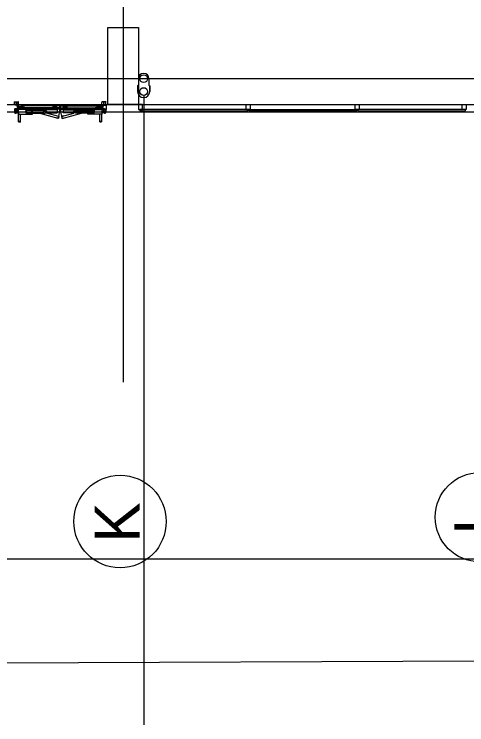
# Model space of a CAD drawing. Extents: x -264031 to -263588, y -1242281 to -1242059.
# Drawn here: x -263850.59 to -263841.78, y -1242253.37 to -1242239.55 of the extents above; entities that cross this region are included whole.
import ezdxf

# ---------------------------------------------------------------- set-up
doc = ezdxf.new("R2010")
doc.units = 0
for name, color, linetype in [('HESCON_OSI_STAVBY_KFA', 7, 'Continuous'), ('KFA_2D_SITUACIA_DSP', 7, 'Continuous'), ('KFA_JESTV_IS_DSP_-_KANAL_SPLASK', 7, 'Continuous')]:
    doc.layers.add(name, color=color, linetype=linetype)

msp = doc.modelspace()

# ---------------------------------------------------------------- linework, layer by layer
at = {"layer": 'HESCON_OSI_STAVBY_KFA'}
for p, q in [((-263848.468, -1242083.237), (-263848.468, -1242246.707)), ((-263792.653, -1242240.807), (-263911.523, -1242240.807))]:
    msp.add_line(p, q, dxfattribs=at)
for centre, radius in [((-263848.528, -1242249.416), 0.899), ((-263841.528, -1242249.331), 0.867)]:
    msp.add_circle(centre, radius, dxfattribs=at)
at = {"layer": 'KFA_2D_SITUACIA_DSP'}
for p, q in [((-263848.768, -1242241.312), (-263848.768, -1242239.812)), ((-263848.768, -1242239.812), (-263848.168, -1242239.812)), ((-263848.168, -1242239.812), (-263848.168, -1242241.312)), ((-263848.171, -1242240.807), (-263848.171, -1242240.932)), ((-263847.965, -1242240.807), (-263847.965, -1242240.932)), ((-263848.171, -1242240.932), (-263848.185, -1242240.946)), ((-263848.185, -1242240.946), (-263848.185, -1242241.057)), ((-263847.965, -1242240.932), (-263847.951, -1242240.946)), ((-263847.951, -1242240.946), (-263847.951, -1242241.057)), ((-263847.951, -1242241.057), (-263847.951, -1242240.946)), ((-263850.587, -1242241.257), (-263850.511, -1242241.257)), ((-263850.581, -1242241.317), (-263850.581, -1242241.257)), ((-263848.798, -1242241.257), (-263848.874, -1242241.257)), ((-263848.804, -1242241.317), (-263848.804, -1242241.257)), ((-263848.068, -1242241.132), (-263848.068, -1242253.366)), ((-263894.581, -1242241.307), (-263809.355, -1242241.307)), ((-263849.693, -1242241.317), (-263850.587, -1242241.317)), ((-263849.693, -1242241.397), (-263850.587, -1242241.397)), ((-263850.582, -1242241.397), (-263850.582, -1242241.407)), ((-263850.582, -1242241.397), (-263850.512, -1242241.397)), ((-263850.571, -1242241.325), (-263850.571, -1242241.317)), ((-263850.55, -1242241.325), (-263850.571, -1242241.325)), ((-263850.55, -1242241.39), (-263850.571, -1242241.39)), ((-263850.571, -1242241.397), (-263850.571, -1242241.39)), ((-263850.554, -1242241.282), (-263850.528, -1242241.282)), ((-263850.541, -1242241.295), (-263850.541, -1242241.269)), ((-263850.512, -1242241.397), (-263850.512, -1242241.407)), ((-263850.507, -1242241.397), (-263850.507, -1242241.317)), ((-263850.507, -1242241.345), (-263850.507, -1242241.37)), ((-263850.507, -1242241.345), (-263850.497, -1242241.345)), ((-263850.507, -1242241.37), (-263850.497, -1242241.37)), ((-263850.462, -1242241.383), (-263850.502, -1242241.383)), ((-263850.502, -1242241.413), (-263850.502, -1242241.383)), ((-263850.501, -1242241.317), (-263850.501, -1242241.267)), ((-263850.501, -1242241.397), (-263850.501, -1242241.317)), ((-263850.501, -1242241.413), (-263850.501, -1242241.397)), ((-263850.497, -1242241.345), (-263850.497, -1242241.37)), ((-263850.497, -1242241.356), (-263850.488, -1242241.349)), ((-263850.497, -1242241.358), (-263850.497, -1242241.356)), ((-263850.488, -1242241.365), (-263850.497, -1242241.358)), ((-263850.494, -1242241.373), (-263850.469, -1242241.373)), ((-263850.494, -1242241.383), (-263850.494, -1242241.373)), ((-263850.494, -1242241.383), (-263850.469, -1242241.383)), ((-263850.49, -1242241.363), (-263850.483, -1242241.373)), ((-263850.483, -1242241.373), (-263850.481, -1242241.373)), ((-263850.481, -1242241.373), (-263850.474, -1242241.363)), ((-263850.478, -1242241.367), (-263850.467, -1242241.362)), ((-263850.476, -1242241.349), (-263850.466, -1242241.356)), ((-263850.466, -1242241.358), (-263850.476, -1242241.365)), ((-263850.467, -1242241.36), (-263850.474, -1242241.351)), ((-263850.47, -1242241.373), (-263850.464, -1242241.349)), ((-263850.461, -1242241.376), (-263850.47, -1242241.373)), ((-263850.469, -1242241.383), (-263850.469, -1242241.373)), ((-263850.467, -1242241.362), (-263850.467, -1242241.36)), ((-263850.456, -1242241.345), (-263850.466, -1242241.345)), ((-263850.466, -1242241.345), (-263850.466, -1242241.37)), ((-263850.466, -1242241.356), (-263850.466, -1242241.358)), ((-263850.456, -1242241.37), (-263850.466, -1242241.37)), ((-263850.454, -1242241.352), (-263850.464, -1242241.349)), ((-263850.452, -1242241.345), (-263850.463, -1242241.383)), ((-263850.41, -1242241.397), (-263850.463, -1242241.383)), ((-263850.462, -1242241.412), (-263850.462, -1242241.383)), ((-263849.698, -1242241.337), (-263850.456, -1242241.337)), ((-263850.456, -1242241.377), (-263850.456, -1242241.337)), ((-263850.456, -1242241.345), (-263850.456, -1242241.37)), ((-263849.698, -1242241.377), (-263850.456, -1242241.377)), ((-263850.255, -1242241.397), (-263850.452, -1242241.345)), ((-263849.755, -1242241.343), (-263849.83, -1242241.343)), ((-263849.83, -1242241.397), (-263849.83, -1242241.343)), ((-263849.83, -1242241.403), (-263849.83, -1242241.397)), ((-263849.819, -1242241.35), (-263849.823, -1242241.357)), ((-263849.823, -1242241.357), (-263849.819, -1242241.364)), ((-263849.812, -1242241.35), (-263849.819, -1242241.35)), ((-263849.819, -1242241.364), (-263849.812, -1242241.364)), ((-263849.808, -1242241.357), (-263849.812, -1242241.35)), ((-263849.812, -1242241.364), (-263849.808, -1242241.357)), ((-263849.774, -1242241.35), (-263849.778, -1242241.357)), ((-263849.778, -1242241.357), (-263849.774, -1242241.364)), ((-263849.767, -1242241.35), (-263849.774, -1242241.35)), ((-263849.774, -1242241.364), (-263849.767, -1242241.364)), ((-263849.763, -1242241.357), (-263849.767, -1242241.35)), ((-263849.767, -1242241.364), (-263849.763, -1242241.357)), ((-263849.755, -1242241.397), (-263849.755, -1242241.343)), ((-263849.755, -1242241.403), (-263849.755, -1242241.397)), ((-263849.7, -1242241.335), (-263849.73, -1242241.335)), ((-263849.73, -1242241.337), (-263849.73, -1242241.335)), ((-263849.73, -1242241.379), (-263849.73, -1242241.377)), ((-263849.7, -1242241.379), (-263849.73, -1242241.379)), ((-263849.715, -1242241.38), (-263849.715, -1242241.377)), ((-263849.7, -1242241.374), (-263849.7, -1242241.383)), ((-263849.698, -1242241.377), (-263849.698, -1242241.337)), ((-263849.696, -1242241.375), (-263849.696, -1242241.339)), ((-263849.693, -1242241.317), (-263848.798, -1242241.317)), ((-263849.693, -1242241.397), (-263848.798, -1242241.397)), ((-263849.69, -1242241.375), (-263849.69, -1242241.339)), ((-263849.688, -1242241.337), (-263848.929, -1242241.337)), ((-263849.688, -1242241.377), (-263849.688, -1242241.337)), ((-263849.688, -1242241.377), (-263848.929, -1242241.377)), ((-263849.686, -1242241.335), (-263849.656, -1242241.335)), ((-263849.686, -1242241.374), (-263849.686, -1242241.383)), ((-263849.686, -1242241.379), (-263849.656, -1242241.379)), ((-263849.671, -1242241.38), (-263849.671, -1242241.377)), ((-263849.656, -1242241.337), (-263849.656, -1242241.335)), ((-263849.656, -1242241.379), (-263849.656, -1242241.377)), ((-263849.63, -1242241.343), (-263849.555, -1242241.343)), ((-263849.63, -1242241.397), (-263849.63, -1242241.343)), ((-263849.63, -1242241.403), (-263849.63, -1242241.397)), ((-263849.623, -1242241.357), (-263849.619, -1242241.35)), ((-263849.619, -1242241.364), (-263849.623, -1242241.357)), ((-263849.619, -1242241.35), (-263849.612, -1242241.35)), ((-263849.612, -1242241.364), (-263849.619, -1242241.364)), ((-263849.612, -1242241.35), (-263849.608, -1242241.357)), ((-263849.608, -1242241.357), (-263849.612, -1242241.364)), ((-263849.578, -1242241.357), (-263849.574, -1242241.35)), ((-263849.574, -1242241.364), (-263849.578, -1242241.357)), ((-263849.574, -1242241.35), (-263849.567, -1242241.35)), ((-263849.567, -1242241.364), (-263849.574, -1242241.364)), ((-263849.567, -1242241.35), (-263849.563, -1242241.357)), ((-263849.563, -1242241.357), (-263849.567, -1242241.364)), ((-263849.555, -1242241.397), (-263849.555, -1242241.343)), ((-263849.555, -1242241.403), (-263849.555, -1242241.397)), ((-263849.131, -1242241.397), (-263848.934, -1242241.345)), ((-263848.976, -1242241.397), (-263848.923, -1242241.383)), ((-263848.934, -1242241.345), (-263848.923, -1242241.383)), ((-263848.932, -1242241.352), (-263848.922, -1242241.349)), ((-263848.929, -1242241.377), (-263848.929, -1242241.337)), ((-263848.929, -1242241.345), (-263848.919, -1242241.345)), ((-263848.929, -1242241.345), (-263848.929, -1242241.37)), ((-263848.929, -1242241.37), (-263848.919, -1242241.37)), ((-263848.925, -1242241.376), (-263848.916, -1242241.373)), ((-263848.924, -1242241.383), (-263848.884, -1242241.383)), ((-263848.924, -1242241.412), (-263848.924, -1242241.383)), ((-263848.916, -1242241.373), (-263848.922, -1242241.349)), ((-263848.919, -1242241.345), (-263848.919, -1242241.37)), ((-263848.91, -1242241.349), (-263848.919, -1242241.356)), ((-263848.919, -1242241.36), (-263848.912, -1242241.351)), ((-263848.919, -1242241.356), (-263848.919, -1242241.358)), ((-263848.919, -1242241.358), (-263848.91, -1242241.365)), ((-263848.919, -1242241.362), (-263848.919, -1242241.36)), ((-263848.908, -1242241.367), (-263848.919, -1242241.362)), ((-263848.891, -1242241.373), (-263848.916, -1242241.373)), ((-263848.916, -1242241.383), (-263848.916, -1242241.373)), ((-263848.891, -1242241.383), (-263848.916, -1242241.383)), ((-263848.905, -1242241.373), (-263848.912, -1242241.363)), ((-263848.903, -1242241.373), (-263848.905, -1242241.373)), ((-263848.896, -1242241.363), (-263848.903, -1242241.373)), ((-263848.888, -1242241.356), (-263848.898, -1242241.349)), ((-263848.898, -1242241.365), (-263848.888, -1242241.358)), ((-263848.891, -1242241.383), (-263848.891, -1242241.373)), ((-263848.888, -1242241.345), (-263848.888, -1242241.37)), ((-263848.878, -1242241.345), (-263848.888, -1242241.345)), ((-263848.888, -1242241.358), (-263848.888, -1242241.356)), ((-263848.878, -1242241.37), (-263848.888, -1242241.37)), ((-263848.884, -1242241.317), (-263848.884, -1242241.267)), ((-263848.884, -1242241.397), (-263848.884, -1242241.317)), ((-263848.884, -1242241.413), (-263848.884, -1242241.383)), ((-263848.884, -1242241.413), (-263848.884, -1242241.397)), ((-263848.878, -1242241.397), (-263848.878, -1242241.317)), ((-263848.878, -1242241.345), (-263848.878, -1242241.37)), ((-263848.873, -1242241.397), (-263848.873, -1242241.407)), ((-263848.803, -1242241.397), (-263848.873, -1242241.397)), ((-263848.831, -1242241.282), (-263848.857, -1242241.282)), ((-263848.844, -1242241.295), (-263848.844, -1242241.269)), ((-263848.835, -1242241.325), (-263848.814, -1242241.325)), ((-263848.835, -1242241.39), (-263848.814, -1242241.39)), ((-263848.814, -1242241.325), (-263848.814, -1242241.317)), ((-263848.814, -1242241.397), (-263848.814, -1242241.39)), ((-263848.803, -1242241.397), (-263848.803, -1242241.407)), ((-263848.798, -1242241.307), (-263848.798, -1242241.407)), ((-263848.168, -1242241.312), (-263848.768, -1242241.312)), ((-263848.088, -1242241.307), (-263848.168, -1242241.307)), ((-263848.168, -1242241.307), (-263848.168, -1242241.407)), ((-263848.088, -1242241.407), (-263848.088, -1242241.307)), ((-263846.073, -1242241.407), (-263846.073, -1242241.307)), ((-263846.073, -1242241.307), (-263845.993, -1242241.307)), ((-263845.993, -1242241.307), (-263845.993, -1242241.407)), ((-263843.953, -1242241.407), (-263843.953, -1242241.307)), ((-263843.953, -1242241.307), (-263843.873, -1242241.307)), ((-263843.873, -1242241.307), (-263843.873, -1242241.407)), ((-263841.873, -1242241.407), (-263841.873, -1242241.307)), ((-263841.873, -1242241.307), (-263841.793, -1242241.307)), ((-263841.793, -1242241.307), (-263841.793, -1242241.407)), ((-263850.582, -1242241.407), (-263850.582, -1242241.457)), ((-263850.582, -1242241.407), (-263850.512, -1242241.407)), ((-263850.564, -1242241.407), (-263850.58, -1242241.407)), ((-263850.58, -1242241.409), (-263850.58, -1242241.407)), ((-263850.564, -1242241.409), (-263850.58, -1242241.409)), ((-263850.565, -1242241.409), (-263850.579, -1242241.409)), ((-263850.579, -1242241.409), (-263850.579, -1242241.415)), ((-263850.579, -1242241.415), (-263850.565, -1242241.415)), ((-263850.578, -1242241.457), (-263850.546, -1242241.457)), ((-263850.572, -1242241.417), (-263850.572, -1242241.403)), ((-263850.572, -1242241.409), (-263850.572, -1242241.414)), ((-263850.572, -1242241.451), (-263850.562, -1242241.445)), ((-263850.572, -1242241.463), (-263850.572, -1242241.451)), ((-263850.562, -1242241.469), (-263850.572, -1242241.463)), ((-263850.565, -1242241.415), (-263850.565, -1242241.409)), ((-263850.564, -1242241.409), (-263850.564, -1242241.407)), ((-263850.506, -1242241.441), (-263850.562, -1242241.442)), ((-263850.562, -1242241.473), (-263850.562, -1242241.442)), ((-263850.562, -1242241.445), (-263850.552, -1242241.451)), ((-263850.552, -1242241.463), (-263850.562, -1242241.469)), ((-263850.562, -1242241.472), (-263850.506, -1242241.471)), ((-263850.552, -1242241.451), (-263850.552, -1242241.463)), ((-263850.542, -1242241.407), (-263850.542, -1242241.442)), ((-263850.542, -1242241.432), (-263850.532, -1242241.432)), ((-263850.541, -1242241.442), (-263850.541, -1242241.423)), ((-263850.515, -1242241.407), (-263850.531, -1242241.407)), ((-263850.531, -1242241.409), (-263850.531, -1242241.407)), ((-263850.515, -1242241.409), (-263850.531, -1242241.409)), ((-263850.516, -1242241.409), (-263850.53, -1242241.409)), ((-263850.53, -1242241.409), (-263850.53, -1242241.415)), ((-263850.53, -1242241.415), (-263850.516, -1242241.415)), ((-263850.523, -1242241.417), (-263850.523, -1242241.403)), ((-263850.523, -1242241.409), (-263850.523, -1242241.414)), ((-263850.516, -1242241.415), (-263850.516, -1242241.409)), ((-263850.515, -1242241.409), (-263850.515, -1242241.407)), ((-263850.232, -1242241.407), (-263850.507, -1242241.413)), ((-263850.507, -1242241.413), (-263850.505, -1242241.5)), ((-263850.505, -1242241.5), (-263850.23, -1242241.494)), ((-263850.502, -1242241.643), (-263850.502, -1242241.5)), ((-263850.462, -1242241.643), (-263850.462, -1242241.499)), ((-263850.232, -1242241.426), (-263850.358, -1242241.428)), ((-263850.357, -1242241.478), (-263850.358, -1242241.428)), ((-263850.231, -1242241.476), (-263850.357, -1242241.478)), ((-263850.347, -1242241.478), (-263850.348, -1242241.428)), ((-263850.241, -1242241.476), (-263850.242, -1242241.426)), ((-263850.23, -1242241.494), (-263850.232, -1242241.407)), ((-263849.751, -1242241.411), (-263850.232, -1242241.42)), ((-263850.009, -1242241.426), (-263850.231, -1242241.431)), ((-263850.008, -1242241.466), (-263850.231, -1242241.471)), ((-263850.23, -1242241.481), (-263849.75, -1242241.472)), ((-263849.729, -1242241.578), (-263850.106, -1242241.479)), ((-263850.008, -1242241.466), (-263850.009, -1242241.426)), ((-263850.003, -1242241.436), (-263850.008, -1242241.436)), ((-263850.003, -1242241.456), (-263850.008, -1242241.456)), ((-263850.003, -1242241.456), (-263850.003, -1242241.436)), ((-263849.996, -1242241.436), (-263850.003, -1242241.436)), ((-263850.003, -1242241.438), (-263850.003, -1242241.436)), ((-263850.003, -1242241.455), (-263850.003, -1242241.438)), ((-263849.996, -1242241.441), (-263850.003, -1242241.441)), ((-263850.003, -1242241.455), (-263850.002, -1242241.456)), ((-263849.996, -1242241.451), (-263850.002, -1242241.451)), ((-263849.996, -1242241.456), (-263850.002, -1242241.456)), ((-263849.995, -1242241.437), (-263849.996, -1242241.436)), ((-263849.995, -1242241.454), (-263849.996, -1242241.456)), ((-263849.995, -1242241.454), (-263849.995, -1242241.437)), ((-263849.987, -1242241.441), (-263849.995, -1242241.441)), ((-263849.987, -1242241.451), (-263849.995, -1242241.451)), ((-263849.987, -1242241.441), (-263849.974, -1242241.433)), ((-263849.987, -1242241.441), (-263849.987, -1242241.451)), ((-263849.987, -1242241.451), (-263849.974, -1242241.458)), ((-263849.719, -1242241.539), (-263849.962, -1242241.476)), ((-263849.755, -1242241.403), (-263849.83, -1242241.403)), ((-263849.751, -1242241.411), (-263849.75, -1242241.472)), ((-263849.75, -1242241.531), (-263849.749, -1242241.529)), ((-263849.749, -1242241.529), (-263849.72, -1242241.536)), ((-263849.667, -1242241.539), (-263849.424, -1242241.476)), ((-263849.636, -1242241.529), (-263849.665, -1242241.536)), ((-263849.657, -1242241.578), (-263849.28, -1242241.479)), ((-263849.635, -1242241.411), (-263849.636, -1242241.472)), ((-263849.156, -1242241.481), (-263849.636, -1242241.472)), ((-263849.636, -1242241.531), (-263849.636, -1242241.529)), ((-263849.635, -1242241.411), (-263849.154, -1242241.42)), ((-263849.63, -1242241.403), (-263849.555, -1242241.403)), ((-263849.399, -1242241.441), (-263849.412, -1242241.433)), ((-263849.399, -1242241.451), (-263849.412, -1242241.458)), ((-263849.399, -1242241.441), (-263849.399, -1242241.451)), ((-263849.399, -1242241.441), (-263849.391, -1242241.441)), ((-263849.399, -1242241.451), (-263849.391, -1242241.451)), ((-263849.391, -1242241.437), (-263849.39, -1242241.436)), ((-263849.391, -1242241.454), (-263849.391, -1242241.437)), ((-263849.391, -1242241.454), (-263849.39, -1242241.456)), ((-263849.39, -1242241.436), (-263849.383, -1242241.436)), ((-263849.39, -1242241.441), (-263849.383, -1242241.441)), ((-263849.39, -1242241.451), (-263849.384, -1242241.451)), ((-263849.39, -1242241.456), (-263849.384, -1242241.456)), ((-263849.383, -1242241.455), (-263849.384, -1242241.456)), ((-263849.383, -1242241.436), (-263849.378, -1242241.436)), ((-263849.383, -1242241.456), (-263849.383, -1242241.436)), ((-263849.383, -1242241.438), (-263849.383, -1242241.436)), ((-263849.383, -1242241.455), (-263849.383, -1242241.438)), ((-263849.383, -1242241.456), (-263849.378, -1242241.456)), ((-263849.378, -1242241.466), (-263849.377, -1242241.426)), ((-263849.378, -1242241.466), (-263849.155, -1242241.471)), ((-263849.377, -1242241.426), (-263849.155, -1242241.431)), ((-263849.156, -1242241.494), (-263849.154, -1242241.407)), ((-263848.881, -1242241.5), (-263849.156, -1242241.494)), ((-263849.155, -1242241.476), (-263849.029, -1242241.478)), ((-263849.154, -1242241.407), (-263848.879, -1242241.413)), ((-263849.154, -1242241.426), (-263849.028, -1242241.428)), ((-263849.145, -1242241.476), (-263849.144, -1242241.426)), ((-263849.039, -1242241.478), (-263849.038, -1242241.428)), ((-263849.029, -1242241.478), (-263849.028, -1242241.428)), ((-263848.924, -1242241.643), (-263848.924, -1242241.499)), ((-263848.884, -1242241.643), (-263848.884, -1242241.5)), ((-263848.879, -1242241.413), (-263848.881, -1242241.5)), ((-263848.88, -1242241.441), (-263848.824, -1242241.442)), ((-263848.824, -1242241.472), (-263848.88, -1242241.471)), ((-263848.803, -1242241.407), (-263848.873, -1242241.407)), ((-263848.871, -1242241.407), (-263848.855, -1242241.407)), ((-263848.871, -1242241.409), (-263848.871, -1242241.407)), ((-263848.871, -1242241.409), (-263848.855, -1242241.409)), ((-263848.87, -1242241.409), (-263848.856, -1242241.409)), ((-263848.87, -1242241.415), (-263848.87, -1242241.409)), ((-263848.856, -1242241.415), (-263848.87, -1242241.415)), ((-263848.863, -1242241.417), (-263848.863, -1242241.403)), ((-263848.863, -1242241.409), (-263848.863, -1242241.414)), ((-263848.856, -1242241.409), (-263848.856, -1242241.415)), ((-263848.855, -1242241.409), (-263848.855, -1242241.407)), ((-263848.844, -1242241.432), (-263848.854, -1242241.432)), ((-263848.844, -1242241.407), (-263848.844, -1242241.442)), ((-263848.844, -1242241.442), (-263848.844, -1242241.423)), ((-263848.808, -1242241.457), (-263848.84, -1242241.457)), ((-263848.824, -1242241.445), (-263848.834, -1242241.451)), ((-263848.834, -1242241.451), (-263848.834, -1242241.463)), ((-263848.834, -1242241.463), (-263848.824, -1242241.469)), ((-263848.824, -1242241.473), (-263848.824, -1242241.442)), ((-263848.814, -1242241.451), (-263848.824, -1242241.445)), ((-263848.824, -1242241.469), (-263848.814, -1242241.463)), ((-263848.822, -1242241.407), (-263848.806, -1242241.407)), ((-263848.822, -1242241.409), (-263848.822, -1242241.407)), ((-263848.822, -1242241.409), (-263848.806, -1242241.409)), ((-263848.821, -1242241.409), (-263848.807, -1242241.409)), ((-263848.821, -1242241.415), (-263848.821, -1242241.409)), ((-263848.807, -1242241.415), (-263848.821, -1242241.415)), ((-263848.814, -1242241.417), (-263848.814, -1242241.403)), ((-263848.814, -1242241.409), (-263848.814, -1242241.414)), ((-263848.814, -1242241.463), (-263848.814, -1242241.451)), ((-263848.807, -1242241.409), (-263848.807, -1242241.415)), ((-263848.806, -1242241.409), (-263848.806, -1242241.407)), ((-263848.804, -1242241.407), (-263848.804, -1242241.457)), ((-263848.168, -1242241.407), (-263848.128, -1242241.407)), ((-263846.043, -1242241.407), (-263848.143, -1242241.407)), ((-263848.143, -1242241.407), (-263848.143, -1242241.432)), ((-263848.143, -1242241.432), (-263846.043, -1242241.432)), ((-263848.128, -1242241.407), (-263848.088, -1242241.407)), ((-263846.083, -1242241.407), (-263846.073, -1242241.407)), ((-263845.993, -1242241.407), (-263846.083, -1242241.407)), ((-263846.043, -1242241.432), (-263846.043, -1242241.407)), ((-263846.023, -1242241.432), (-263846.023, -1242241.407)), ((-263846.023, -1242241.407), (-263843.923, -1242241.407)), ((-263843.923, -1242241.432), (-263846.023, -1242241.432)), ((-263843.913, -1242241.407), (-263843.953, -1242241.407)), ((-263843.923, -1242241.407), (-263843.923, -1242241.432)), ((-263843.873, -1242241.407), (-263843.913, -1242241.407)), ((-263841.803, -1242241.407), (-263843.903, -1242241.407)), ((-263843.903, -1242241.407), (-263843.903, -1242241.432)), ((-263843.903, -1242241.432), (-263841.803, -1242241.432)), ((-263841.833, -1242241.407), (-263841.873, -1242241.407)), ((-263841.793, -1242241.407), (-263841.833, -1242241.407)), ((-263841.803, -1242241.432), (-263841.803, -1242241.407)), ((-263850.502, -1242241.643), (-263850.49, -1242241.643)), ((-263850.49, -1242241.643), (-263850.486, -1242241.628)), ((-263850.486, -1242241.628), (-263850.478, -1242241.658)), ((-263850.478, -1242241.658), (-263850.474, -1242241.643)), ((-263850.474, -1242241.643), (-263850.462, -1242241.643)), ((-263849.761, -1242241.571), (-263849.76, -1242241.569)), ((-263849.732, -1242241.579), (-263849.761, -1242241.571)), ((-263849.719, -1242241.539), (-263849.729, -1242241.578)), ((-263849.718, -1242241.541), (-263849.727, -1242241.576)), ((-263849.668, -1242241.541), (-263849.659, -1242241.576)), ((-263849.667, -1242241.539), (-263849.657, -1242241.578)), ((-263849.654, -1242241.579), (-263849.625, -1242241.571)), ((-263849.625, -1242241.571), (-263849.626, -1242241.569)), ((-263848.912, -1242241.643), (-263848.924, -1242241.643)), ((-263848.908, -1242241.658), (-263848.912, -1242241.643)), ((-263848.9, -1242241.628), (-263848.908, -1242241.658)), ((-263848.896, -1242241.643), (-263848.9, -1242241.628)), ((-263848.884, -1242241.643), (-263848.896, -1242241.643)), ((-263924.143, -1242250.14), (-263788.143, -1242250.14))]:
    msp.add_line(p, q, dxfattribs=at)
msp.add_lwpolyline([(-263794.893, -1242227.382), (-263808.968, -1242241.457), (-263894.968, -1242241.457), (-263909.043, -1242227.382), (-263909.043, -1242196.333), (-263914.143, -1242196.333), (-263914.143, -1242132.433), (-263909.043, -1242132.433), (-263909.043, -1242101.382), (-263894.968, -1242087.307), (-263808.968, -1242087.307), (-263794.893, -1242101.382), (-263794.893, -1242227.382)], dxfattribs=at)
for centre, radius in [((-263848.068, -1242240.807), 0.075), ((-263848.068, -1242241.057), 0.075), ((-263850.541, -1242241.282), 0.008), ((-263849.815, -1242241.357), 0.0084), ((-263849.815, -1242241.357), 0.0068), ((-263849.77, -1242241.357), 0.0084), ((-263849.77, -1242241.357), 0.0068), ((-263849.615, -1242241.357), 0.0084), ((-263849.615, -1242241.357), 0.0068), ((-263849.57, -1242241.357), 0.0084), ((-263849.57, -1242241.357), 0.0068), ((-263850.562, -1242241.457), 0.0126), ((-263850.562, -1242241.457), 0.0102), ((-263849.967, -1242241.445), 0.00952), ((-263849.967, -1242241.445), 0.00645), ((-263849.967, -1242241.445), 0.005), ((-263849.419, -1242241.445), 0.00952), ((-263849.419, -1242241.445), 0.00645), ((-263849.419, -1242241.445), 0.005), ((-263848.824, -1242241.457), 0.0126), ((-263848.824, -1242241.457), 0.0102)]:
    msp.add_circle(centre, radius, dxfattribs=at)
for centre, radius, start, end in [((-263848.068, -1242240.807), 0.103, 360, 180), ((-263848.068, -1242241.057), 0.117, 180, 360), ((-263850.511, -1242241.267), 0.01, 0, 90), ((-263848.874, -1242241.267), 0.01, 90, 180), ((-263850.55, -1242241.357), 0.0325, 270, 90), ((-263850.482, -1242241.357), 0.01, 53.6139, 306.3861), ((-263850.482, -1242241.357), 0.01, 323.6139, 216.3861), ((-263850.482, -1242241.357), 0.01, 38.6139, 291.3861), ((-263850.482, -1242241.357), 0.01, 233.6139, 126.3861), ((-263850.482, -1242241.357), 0.786, 345, 0), ((-263849.7, -1242241.339), 0.004, 0, 90), ((-263849.7, -1242241.375), 0.004, 270, 0), ((-263849.686, -1242241.339), 0.004, 90, 180), ((-263848.904, -1242241.357), 0.786, 180, 195), ((-263849.686, -1242241.375), 0.004, 180, 270), ((-263848.904, -1242241.357), 0.01, 53.6139, 306.3861), ((-263848.904, -1242241.357), 0.01, 323.6139, 216.3861), ((-263848.904, -1242241.357), 0.01, 248.6139, 141.3861), ((-263848.904, -1242241.357), 0.01, 233.6139, 126.3861), ((-263848.835, -1242241.357), 0.0325, 90, 270), ((-263850.562, -1242241.457), 0.02, 180, 312.5496), ((-263850.575, -1242241.408), 0.0068, 240, 300), ((-263850.562, -1242241.457), 0.015, 91.14, 271.14), ((-263850.569, -1242241.408), 0.0068, 240, 300), ((-263850.541, -1242241.432), 0.008, 266.4167, 93.5833), ((-263850.526, -1242241.408), 0.0068, 240, 300), ((-263850.52, -1242241.408), 0.0068, 240, 300), ((-263849.999, -1242241.439), 0.00432, 146.5466, 215.7334), ((-263849.987, -1242241.446), 0.0161, 163.4401, 198.8399), ((-263849.999, -1242241.453), 0.00432, 146.5466, 215.7334), ((-263850.002, -1242241.451), 0.0001, 21.9532, 91.14), ((-263850, -1242241.439), 0.00432, 326.5466, 35.7334), ((-263850.011, -1242241.446), 0.0161, 343.4401, 18.8399), ((-263849.999, -1242241.453), 0.00432, 326.5466, 35.7334), ((-263849.996, -1242241.451), 0.0001, 91.14, 160.3268), ((-263849.967, -1242241.445), 0.014, 242.4029, 119.8771), ((-263849.722, -1242241.54), 0.004, 345, 75), ((-263849.664, -1242241.54), 0.004, 105, 195), ((-263849.419, -1242241.445), 0.014, 60.1229, 297.5971), ((-263849.386, -1242241.439), 0.00432, 144.2666, 213.4534), ((-263849.375, -1242241.446), 0.0161, 161.1601, 196.5599), ((-263849.387, -1242241.453), 0.00432, 144.2666, 213.4534), ((-263849.39, -1242241.451), 0.0001, 19.6732, 88.86), ((-263849.399, -1242241.446), 0.0161, 341.1601, 16.5599), ((-263849.387, -1242241.453), 0.00432, 324.2666, 33.4534), ((-263849.384, -1242241.451), 0.0001, 88.86, 158.0468), ((-263849.387, -1242241.439), 0.00432, 324.2666, 33.4534), ((-263848.866, -1242241.408), 0.0068, 240, 300), ((-263848.86, -1242241.408), 0.0068, 240, 300), ((-263848.844, -1242241.432), 0.008, 86.4167, 273.5833), ((-263848.824, -1242241.457), 0.02, 227.4504, 0), ((-263848.824, -1242241.457), 0.015, 268.86, 88.86), ((-263848.817, -1242241.408), 0.0068, 240, 300), ((-263848.811, -1242241.408), 0.0068, 240, 300), ((-263849.731, -1242241.575), 0.004, 255, 345), ((-263849.655, -1242241.575), 0.004, 195, 285)]:
    msp.add_arc(centre, radius, start, end, dxfattribs=at)
at = {"layer": 'KFA_JESTV_IS_DSP_-_KANAL_SPLASK'}
msp.add_line((-263832.703, -1242252.091), (-263876.504, -1242252.281), dxfattribs=at)

# ---------------------------------------------------------------- texts
at = {"layer": 'HESCON_OSI_STAVBY_KFA'}
for s, p in [('K', (-263848.147, -1242249.824)), ('L', (-263841.147, -1242249.671))]:
    msp.add_text(s, height=0.875, rotation=90, dxfattribs=at).set_placement(p)

doc.saveas('drawing.dxf')
